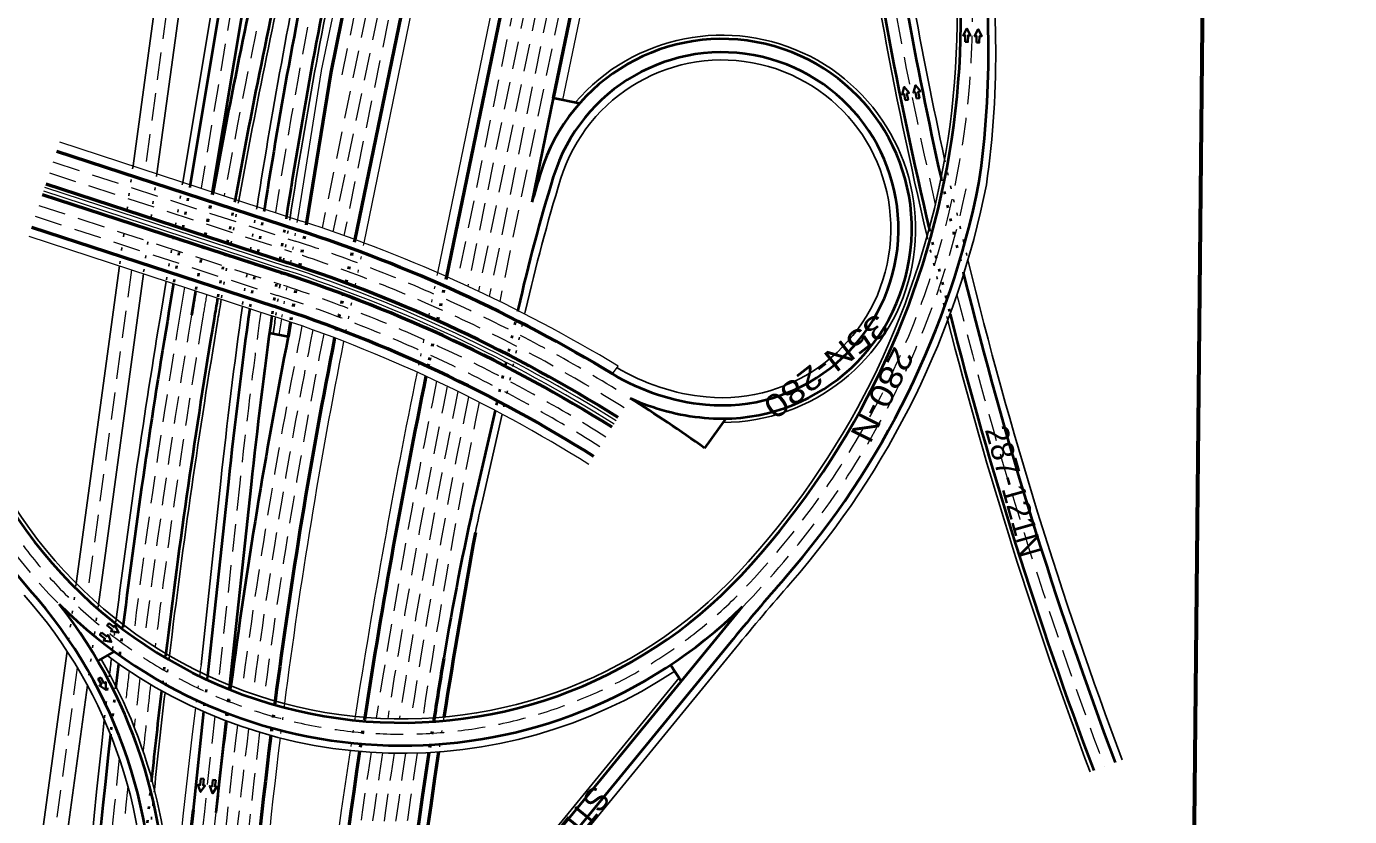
# Model space of a CAD drawing. Extents: x 2329387 to 2347382, y 6951580 to 6987999.
# Drawn here: x 2331366 to 2332753, y 6960345 to 6961173 of the extents above; entities that cross this region are included whole.
import ezdxf

# ---------------------------------------------------------------- set-up
doc = ezdxf.new("R2010")
doc.units = 0
doc.header["$LTSCALE"] = 9.6
doc.linetypes.add('DOTTED', pattern=[1.5, 0.3, -1.2])
doc.linetypes.add('MEDIUM_DASHED', pattern=[4.5, 3, -1.5])
for name, color, linetype, lineweight in [('26', 7, 'Continuous', 53), ('27', 7, 'Continuous', 40), ('41', 7, 'Continuous', 35), ('50', 7, 'MEDIUM_DASHED', 13), ('62', 7, 'Continuous', 60), ('63', 7, 'Continuous', 25)]:
    doc.layers.add(name, color=color, linetype=linetype, lineweight=lineweight)
doc.layers.add('40', color=7, linetype='Continuous')

msp = doc.modelspace()

# ---------------------------------------------------------------- linework, layer by layer
at = {"layer": '26', "lineweight": 13}
for p, q in [((2331724.458, 6961366.169), (2331675.26, 6961127.125)), ((2331802.815, 6961350.042), (2331719.775, 6960946.564)), ((2331883.115, 6961333.431), (2331797.054, 6960915.276)), ((2331973.227, 6961314.885), (2331928.251, 6961096.357)), ((2331675.253, 6961127.09), (2331650.138, 6960970.928)), ((2331400.74, 6961052.344), (2331654.558, 6960969.431)), ((2331383.972, 6961001.013), (2331637.791, 6960918.1)), ((2331385.214, 6961004.815), (2331639.033, 6960921.903)), ((2331368.447, 6960953.485), (2331622.265, 6960870.572)), ((2331633.423, 6960866.999), (2331630.744, 6960850.34)), ((2331980.676, 6960809.191), (2331986.398, 6960817.417))]:
    msp.add_line(p, q, dxfattribs=at)
at = {"layer": '26'}
for p, q in [((2331734.252, 6961364.153), (2331685.095, 6961125.305)), ((2331734.252, 6961364.153), (2331685.095, 6961125.305)), ((2331793.021, 6961352.058), (2331710.29, 6960950.086)), ((2331892.91, 6961331.415), (2331806.417, 6960911.164)), ((2331963.432, 6961316.901), (2331918.456, 6961098.373)), ((2331685.095, 6961125.305), (2331659.765, 6960967.813)), ((2331397.635, 6961042.838), (2331651.453, 6960959.925)), ((2331386.456, 6961008.618), (2331640.275, 6960925.705)), ((2331382.73, 6960997.211), (2331636.549, 6960914.298)), ((2331371.552, 6960962.99), (2331625.37, 6960880.078)), ((2331643.035, 6960863.784), (2331640.561, 6960848.405))]:
    msp.add_line(p, q, dxfattribs=at)
at = {"layer": '26', "linetype": 'DOTTED', "lineweight": 13}
for p, q in [((2331650.138, 6960970.928), (2331633.423, 6960866.999)), ((2331719.775, 6960946.564), (2331706.79, 6960883.472)), ((2331797.054, 6960915.276), (2331777.711, 6960821.292))]:
    msp.add_line(p, q, dxfattribs=at)
at = {"layer": '26', "linetype": 'DOTTED'}
for p, q in [((2331659.765, 6960967.813), (2331643.035, 6960863.784)), ((2331710.29, 6960950.086), (2331697.076, 6960885.882)), ((2331806.417, 6960911.164), (2331787.506, 6960819.276))]:
    msp.add_line(p, q, dxfattribs=at)
at = {"layer": '26'}
for centre, radius, start, end in [((2331155.652, 6959442.139), 1596.714, 58.88878, 71.90983), ((2331155.652, 6959442.139), 1560.714, 57.83887, 71.90983), ((2331155.652, 6959442.139), 1548.714, 57.83887, 71.90983), ((2331155.652, 6959442.139), 1512.714, 57.83887, 71.90983), ((2337309.03, 6959730.876), 5729.578, 168.76752, 172.62557), ((2339270.111, 6959279.267), 7639.437, 168.46618, 171.19128), ((2339270.111, 6959279.267), 7557.437, 169.60454, 171.09176), ((2339270.111, 6959279.267), 7567.437, 170.63176, 171.10996), ((2337309.03, 6959730.876), 5729.578, 172.98959, 183.29735), ((2339270.111, 6959279.267), 7639.437, 171.46189, 181.6147), ((2339270.111, 6959279.267), 7567.437, 171.38894, 177.10146), ((2339270.111, 6959279.267), 7557.437, 171.37243, 178.25098), ((2337309.03, 6959730.876), 5801.578, 173.85545, 181.55357)]:
    msp.add_arc(centre, radius, start, end, dxfattribs=at)
at = {"layer": '26', "lineweight": 13}
for centre, radius, start, end in [((2331155.652, 6959442.139), 1606.714, 58.86565, 71.90983), ((2331155.652, 6959442.139), 1552.714, 57.83887, 71.90983), ((2331155.652, 6959442.139), 1556.714, 57.83887, 71.90983), ((2331155.652, 6959442.139), 1502.714, 57.83887, 71.90983), ((2337309.03, 6959730.876), 5719.578, 168.78475, 172.63974), ((2339270.111, 6959279.267), 7649.437, 168.44885, 171.19593), ((2337309.03, 6959730.876), 5811.578, 172.35225, 172.42899), ((2337309.03, 6959730.876), 5811.578, 172.80217, 181.55357), ((2337309.03, 6959730.876), 5719.578, 173.00338, 183.29735), ((2339270.111, 6959279.267), 7649.437, 171.46588, 181.61718)]:
    msp.add_arc(centre, radius, start, end, dxfattribs=at)
at = {"layer": '26', "linetype": 'DOTTED'}
for centre, radius, start, end in [((2337309.03, 6959730.876), 5729.578, 168.37024, 168.76752), ((2339270.111, 6959279.267), 7639.437, 168.37024, 168.46618), ((2337309.03, 6959730.876), 5729.578, 172.62557, 172.98959), ((2339270.111, 6959279.267), 7639.437, 171.19128, 171.4619), ((2339270.111, 6959279.267), 7567.437, 171.10996, 171.38893)]:
    msp.add_arc(centre, radius, start, end, dxfattribs=at)
at = {"layer": '26', "linetype": 'DOTTED', "lineweight": 13}
for centre, radius, start, end in [((2337309.03, 6959730.876), 5719.578, 168.37024, 168.78475), ((2339270.111, 6959279.267), 7649.437, 168.37024, 168.44885), ((2337309.03, 6959730.876), 5811.578, 172.42899, 172.80218), ((2337309.03, 6959730.876), 5719.578, 172.63974, 173.00338), ((2339270.111, 6959279.267), 7649.437, 171.19593, 171.46588), ((2339270.111, 6959279.267), 7557.437, 171.09175, 171.37243)]:
    msp.add_arc(centre, radius, start, end, dxfattribs=at)
at = {"layer": '27', "lineweight": 25}
for p, q in [((2331775.493, 6962479.35), (2331530.014, 6961010.115)), ((2331512.68, 6960906.369), (2331507.632, 6960876.155)), ((2331864.699, 6960767.055), (2331844.423, 6960677.833)), ((2331569.876, 6960696.854), (2331549.146, 6960504.295)), ((2332109.524, 6960521.717), (2331847.333, 6960201.895)), ((2332050.366, 6960490.566), (2331827.226, 6960218.379))]:
    msp.add_line(p, q, dxfattribs=at)
at = {"layer": '27'}
for p, q in [((2331783.384, 6962478.032), (2331537.705, 6961007.603)), ((2331807.056, 6962474.077), (2331560.779, 6961000.065)), ((2331918.456, 6961098.373), (2331896.031, 6960989.412)), ((2331945.881, 6961092.729), (2331918.456, 6961098.373)), ((2331520.371, 6960903.857), (2331515.523, 6960874.836)), ((2331543.445, 6960896.319), (2331539.195, 6960870.881)), ((2331620.939, 6960852.273), (2331640.561, 6960848.405)), ((2331857.379, 6960770.946), (2331836.622, 6960679.607)), ((2332099.188, 6960762.344), (2332077.092, 6960731.428)), ((2331577.83, 6960695.998), (2331555.958, 6960492.83)), ((2331601.692, 6960693.429), (2331579.015, 6960482.786)), ((2332116.511, 6960564.941), (2331830.32, 6960215.843)), ((2331458.2, 6960518.373), (2331440.929, 6960508.288)), ((2332103.417, 6960526.886), (2331841.147, 6960206.967)), ((2332041.332, 6960504.221), (2332052.676, 6960487.075)), ((2331551.902, 6960455.152), (2331540.782, 6960351.86)), ((2331575.02, 6960445.673), (2331564.644, 6960349.291))]:
    msp.add_line(p, q, dxfattribs=at)
at = {"layer": '27', "linetype": 'DOTTED', "lineweight": 25}
for p, q in [((2331530.014, 6961010.115), (2331512.68, 6960906.369)), ((2331889.412, 6960875.801), (2331864.699, 6960767.055))]:
    msp.add_line(p, q, dxfattribs=at)
at = {"layer": '27', "linetype": 'DOTTED'}
for p, q in [((2331537.705, 6961007.603), (2331520.371, 6960903.857)), ((2331560.779, 6961000.065), (2331543.445, 6960896.319)), ((2331881.613, 6960877.581), (2331857.379, 6960770.946)), ((2331555.958, 6960492.83), (2331551.902, 6960455.152)), ((2331579.015, 6960482.786), (2331575.02, 6960445.673))]:
    msp.add_line(p, q, dxfattribs=at)
at = {"layer": '27'}
for centre, radius, start, end in [((2339406.145, 6959556.474), 7976, 170.51466, 170.51466), ((2331488.314, 6961182.977), 857.473, 316.98269, 21.88176), ((2336798.354, 6962013.709), 4607.662, 187.82614, 193.20332), ((2336798.354, 6962013.709), 4583.662, 187.97272, 192.59319), ((2331429.011, 6961146.766), 945.765, 351.62744, 9.92921), ((2339406.145, 6959556.474), 7976, 167.39024, 169.57492), ((2339406.145, 6959556.474), 7952, 167.39024, 169.5982), ((2337567.201, 6960051.195), 6023.98, 168.01367, 171.10971), ((2337567.201, 6960051.195), 5999.98, 168.01367, 171.14683), ((2332095.311, 6960961.306), 199, 264.63628, 162.90746), ((2332095.311, 6960961.306), 185, 264.63628, 162.90746), ((2333743.985, 6960454.343), 1909.859, 162.90746, 167.19654), ((2333743.985, 6960454.343), 1923.859, 162.90746, 163.85178), ((2331488.314, 6961182.977), 893.473, 318.86471, 348.77516), ((2336798.354, 6962013.709), 4583.662, 193.88538, 200.589), ((2339406.145, 6959556.474), 7976, 170.32943, 170.51466), ((2339406.145, 6959556.474), 7952, 170.35503, 170.51466), ((2339406.145, 6959556.474), 8000, 170.51466, 172.89271), ((2337567.201, 6960051.195), 6023.98, 172.11324, 173.85533), ((2339406.145, 6959556.474), 7952, 170.51466, 173.06921), ((2337567.201, 6960051.195), 5999.98, 172.15449, 173.85532), ((2336798.354, 6962013.709), 4607.662, 194.34791, 200.589), ((2337309.03, 6959730.876), 5777.578, 168.84726, 172.52817), ((2332099.517, 6961006.109), 230, 238.88879, 264.63628), ((2331155.652, 6959442.139), 1584.714, 54.44704, 57.83887), ((2332099.517, 6961006.109), 244, 245.72346, 264.63628), ((2331759.916, 6960929.551), 486, 207.17559, 316.98269), ((2331760.015, 6960929.359), 522, 207.17524, 221.62086), ((2334630.184, 6960044.76), 2864.789, 167.19678, 170.63176), ((2330989.258, 6960244.547), 509.035, 355.35626, 41.62086), ((2334318.881, 6958710.645), 2864.789, 138.86471, 140.65505), ((2331759.916, 6960929.551), 510, 225.19474, 314.36331), ((2330989.258, 6960244.547), 523.035, 355.35626, 38.15909), ((2339406.145, 6959556.474), 8000, 173.18807, 173.3576), ((2339406.145, 6959556.474), 7952, 173.35147, 174.02309), ((2337309.03, 6959730.876), 5777.578, 172.89618, 173.85545), ((2339406.145, 6959556.474), 8000, 173.72103, 179.41614)]:
    msp.add_arc(centre, radius, start, end, dxfattribs=at)
at = {"layer": '27', "lineweight": 25}
for centre, radius, start, end in [((2331488.314, 6961182.977), 853.473, 316.98269, 21.88176), ((2337081.285, 6962065.532), 4898.95, 187.63559, 193.12349), ((2336798.354, 6962013.709), 4575.662, 188.03429, 192.35956), ((2337567.201, 6960051.195), 6031.98, 168.01367, 171.0974), ((2331388.291, 6961146.248), 993.984, 351.97584, 9.5406), ((2339406.145, 6959556.474), 7948, 167.39024, 169.60209), ((2337567.201, 6960051.195), 5995.98, 168.01367, 171.15332), ((2332095.311, 6960961.306), 203, 270.28029, 139.31038), ((2332095.311, 6960961.306), 177, 264.63628, 162.90746), ((2333743.985, 6960454.343), 1901.859, 162.90746, 167.19678), ((2331488.314, 6961182.977), 901.473, 318.86661, 348.77516), ((2336798.354, 6962013.709), 4575.662, 193.71669, 200.589), ((2339406.145, 6959556.474), 8008, 170.51466, 172.85862), ((2339406.145, 6959556.474), 7948, 170.35931, 170.51466), ((2337567.201, 6960051.195), 6031.98, 172.09956, 173.85532), ((2339406.145, 6959556.474), 7948, 170.51466, 173.08188), ((2337567.201, 6960051.195), 5995.98, 172.16092, 172.32966), ((2336798.354, 6962013.709), 4611.662, 194.41946, 200.589), ((2332099.517, 6961006.109), 222, 238.88879, 264.63628), ((2331759.916, 6960929.551), 482, 207.17559, 316.98269), ((2334630.184, 6960044.76), 2856.789, 167.19678, 167.91345), ((2334324.989, 6958705.476), 2864.789, 138.86661, 140.65505), ((2330989.258, 6960244.547), 501.035, 355.35626, 41.62086), ((2331759.916, 6960929.551), 518, 233.34606, 303.49023), ((2330989.258, 6960244.547), 527.035, 355.35626, 30.28163), ((2339406.145, 6959556.474), 8008, 173.15672, 173.2734), ((2339406.145, 6959556.474), 7948, 173.36327, 174.09944), ((2339406.145, 6959556.474), 8008, 173.61844, 179.41614)]:
    msp.add_arc(centre, radius, start, end, dxfattribs=at)
at = {"layer": '27', "linetype": 'DOTTED', "lineweight": 25}
for centre, radius, start, end in [((2336798.354, 6962013.709), 4575.662, 192.35956, 193.71669), ((2339406.145, 6959556.474), 7948, 169.60209, 170.35931), ((2337567.201, 6960051.195), 6031.98, 171.0974, 172.09956), ((2337567.201, 6960051.195), 5995.98, 171.15332, 172.16092), ((2336798.354, 6962013.709), 4611.662, 193.29457, 194.41946), ((2339406.145, 6959556.474), 8008, 172.85862, 173.15672), ((2339406.145, 6959556.474), 7948, 173.08188, 173.36328), ((2339406.145, 6959556.474), 8008, 173.2739, 173.61844), ((2339406.145, 6959556.474), 7948, 174.09944, 174.88074)]:
    msp.add_arc(centre, radius, start, end, dxfattribs=at)
at = {"layer": '27', "linetype": 'DOTTED'}
for centre, radius, start, end in [((2336798.354, 6962013.709), 4583.662, 192.59319, 193.88539), ((2339406.145, 6959556.474), 7976, 169.57492, 170.32943), ((2339406.145, 6959556.474), 7952, 169.5982, 170.35503), ((2337567.201, 6960051.195), 6023.98, 171.10971, 172.11324), ((2337567.201, 6960051.195), 5999.98, 171.14683, 172.15449), ((2336798.354, 6962013.709), 4607.662, 193.20332, 194.34791), ((2339406.145, 6959556.474), 8000, 172.89271, 173.18807), ((2339406.145, 6959556.474), 7952, 173.06921, 173.35147), ((2339406.145, 6959556.474), 8000, 173.3576, 173.72103), ((2337309.03, 6959730.876), 5777.578, 172.52818, 172.89618), ((2339406.145, 6959556.474), 7952, 174.02309, 174.70032)]:
    msp.add_arc(centre, radius, start, end, dxfattribs=at)
at = {"layer": '27', "linetype": 'DOTTED', "lineweight": 13}
msp.add_arc((2339406.145, 6959556.474), 8008, 173.2734, 173.2739, dxfattribs=at)
at = {"layer": '41'}
for points in [[(2332350.116, 6961157.267), (2332353.116, 6961157.207), (2332353.251, 6961164.013), (2332355.688, 6961163.965), (2332352.052, 6961171.238), (2332348.131, 6961164.114), (2332350.251, 6961164.072)], [(2332362.087, 6961156.508), (2332365.087, 6961156.448), (2332365.222, 6961163.254), (2332367.659, 6961163.206), (2332364.023, 6961170.479), (2332360.103, 6961163.355), (2332362.222, 6961163.313)], [(2332287.463, 6961096.002), (2332290.408, 6961096.579), (2332289.097, 6961103.259), (2332291.489, 6961103.728), (2332286.395, 6961110.066), (2332284.073, 6961102.273), (2332286.153, 6961102.681)], [(2332299.323, 6961097.796), (2332302.268, 6961098.373), (2332300.958, 6961105.053), (2332303.349, 6961105.522), (2332298.255, 6961111.86), (2332295.933, 6961104.067), (2332298.013, 6961104.475)], [(2331452.512, 6960547.832), (2331450.687, 6960545.45), (2331456.091, 6960541.31), (2331454.608, 6960539.375), (2331462.622, 6960537.997), (2331459.204, 6960545.375), (2331457.915, 6960543.692)], [(2331444.968, 6960538.105), (2331443.144, 6960535.723), (2331448.547, 6960531.584), (2331447.065, 6960529.649), (2331455.079, 6960528.27), (2331451.661, 6960535.648), (2331450.372, 6960533.966)], [(2331444.113, 6960491.073), (2331441.477, 6960489.639), (2331444.728, 6960483.659), (2331442.587, 6960482.495), (2331449.346, 6960477.974), (2331449.227, 6960486.105), (2331447.364, 6960485.092)], [(2331552.052, 6960384.709), (2331549.073, 6960385.07), (2331548.254, 6960378.313), (2331545.834, 6960378.606), (2331548.72, 6960371.003), (2331553.337, 6960377.697), (2331551.233, 6960377.952)], [(2331564.539, 6960383.239), (2331561.56, 6960383.6), (2331560.741, 6960376.843), (2331558.322, 6960377.136), (2331561.207, 6960369.534), (2331565.824, 6960376.227), (2331563.72, 6960376.482)]]:
    msp.add_lwpolyline(points, close=True, dxfattribs=at)
at = {"layer": '50'}
for p, q in [((2331795.22, 6962476.054), (2331549.242, 6961003.834)), ((2331757.76, 6961359.315), (2331676.038, 6960962.247)), ((2331746.006, 6961361.734), (2331696.848, 6961122.886)), ((2331769.513, 6961356.896), (2331687.474, 6960958.284)), ((2331780.211, 6961349.347), (2331698.891, 6960954.23)), ((2331904.664, 6961328.996), (2331817.635, 6960906.143)), ((2331916.417, 6961326.577), (2331828.834, 6960901.027)), ((2331928.171, 6961324.158), (2331840.013, 6960895.817)), ((2331939.925, 6961321.739), (2331851.173, 6960890.511)), ((2331951.678, 6961319.32), (2331862.312, 6960885.108)), ((2331393.909, 6961031.431), (2331647.727, 6960948.519)), ((2331390.182, 6961020.024), (2331644.001, 6960937.112)), ((2331379.004, 6960985.804), (2331632.822, 6960902.891)), ((2331375.278, 6960974.397), (2331629.096, 6960891.485)), ((2331531.908, 6960900.088), (2331527.359, 6960872.859)), ((2331589.761, 6960694.714), (2331567.468, 6960487.637)), ((2331563.444, 6960450.257), (2331552.713, 6960350.575))]:
    msp.add_line(p, q, dxfattribs=at)
for centre, radius, start, end in [((2336798.354, 6962013.709), 4595.662, 182.32731, 192.91301), ((2331488.314, 6961182.977), 869.473, 316.98269, 21.88176), ((2339406.145, 6959556.474), 7964, 167.39024, 169.58654), ((2337567.201, 6960051.195), 6011.98, 168.01367, 171.12823), ((2331488.314, 6961182.977), 881.473, 315.46714, 348.77516), ((2331155.652, 6959442.139), 1584.714, 58.46734, 71.90983), ((2331155.652, 6959442.139), 1572.714, 57.83887, 71.90983), ((2331155.652, 6959442.139), 1536.714, 57.83887, 71.90983), ((2339406.145, 6959556.474), 7964, 170.34221, 170.51466), ((2331155.652, 6959442.139), 1524.714, 57.83887, 71.90983), ((2336798.354, 6962013.709), 4595.662, 194.12418, 200.589), ((2337567.201, 6960051.195), 6011.98, 172.13383, 173.85544), ((2339406.145, 6959556.474), 7988, 170.51466, 172.94123), ((2339406.145, 6959556.474), 7976, 170.51466, 172.98675), ((2339406.145, 6959556.474), 7964, 170.51466, 173.02937), ((2337309.03, 6959730.876), 5765.578, 168.71169, 172.55713), ((2337309.03, 6959730.876), 5753.578, 168.72924, 172.58299), ((2337309.03, 6959730.876), 5741.578, 168.74784, 172.6058), ((2339270.111, 6959279.267), 7627.437, 168.48775, 171.1836), ((2339270.111, 6959279.267), 7615.437, 168.51018, 171.17362), ((2339270.111, 6959279.267), 7603.437, 168.53347, 171.1613), ((2339270.111, 6959279.267), 7591.437, 168.55764, 171.14662), ((2339270.111, 6959279.267), 7579.437, 168.5827, 171.12952), ((2331759.916, 6960929.551), 510, 207.17525, 225.19472), ((2331759.916, 6960929.551), 498, 207.17525, 316.98269), ((2339406.145, 6959556.474), 7988, 173.23282, 173.49467), ((2339406.145, 6959556.474), 7976, 173.27491, 173.64751), ((2339406.145, 6959556.474), 7964, 173.31444, 173.82091), ((2337309.03, 6959730.876), 5765.578, 172.92379, 183.29735), ((2337309.03, 6959730.876), 5753.578, 172.94854, 183.29735), ((2337309.03, 6959730.876), 5741.578, 172.97047, 183.29735), ((2339406.145, 6959556.474), 7988, 173.8931, 179.41614), ((2339270.111, 6959279.267), 7627.437, 171.45517, 181.61172), ((2339270.111, 6959279.267), 7615.437, 171.44631, 181.60872), ((2339270.111, 6959279.267), 7603.437, 171.43529, 181.60572), ((2339270.111, 6959279.267), 7591.437, 171.42207, 177.10146), ((2339270.111, 6959279.267), 7579.437, 171.40663, 177.10146), ((2339406.145, 6959556.474), 7976, 174.09518, 179.41614), ((2337309.03, 6959730.876), 5789.578, 173.85545, 183.29735), ((2337309.03, 6959730.876), 5777.578, 173.85545, 183.29735)]:
    msp.add_arc(centre, radius, start, end, dxfattribs=at)
at = {"layer": '62'}
msp.add_lwpolyline([(2332642.295, 6965522.154), (2332560.849, 6957416.973), (2330660.943, 6957436.065), (2330739.467, 6965250.394)], close=True, dxfattribs=at)
at = {"layer": '63'}
for p, q in [((2331583.039, 6961607.79), (2331502.947, 6961018.957)), ((2331548.281, 6961545.165), (2331477.824, 6961027.163)), ((2331463.576, 6960922.409), (2331418.298, 6960589.521)), ((2331488.699, 6960914.203), (2331441.562, 6960567.647)), ((2331430.021, 6960482.799), (2331314.438, 6959633.029))]:
    msp.add_line(p, q, dxfattribs=at)
at = {"layer": '63', "linetype": 'MEDIUM_DASHED', "lineweight": 13}
for p, q in [((2331565.355, 6961574.235), (2331490.386, 6961023.06)), ((2331476.138, 6960918.306), (2331429.886, 6960578.262)), ((2331419.434, 6960501.422), (2331301.557, 6959634.781))]:
    msp.add_line(p, q, dxfattribs=at)
at = {"layer": '63', "linetype": 'DOTTED'}
for p, q in [((2331477.824, 6961027.163), (2331463.576, 6960922.409)), ((2331502.947, 6961018.957), (2331488.699, 6960914.203)), ((2331418.298, 6960589.521), (2331408.66, 6960518.661)), ((2331441.562, 6960567.647), (2331430.021, 6960482.799))]:
    msp.add_line(p, q, dxfattribs=at)
at = {"layer": '63'}
msp.add_lwpolyline([(2331408.66, 6960518.661), (2331342.19, 6960029.976), (2331332.504, 6959958.761)], dxfattribs=at)

# ---------------------------------------------------------------- texts
at = {"layer": '40'}
for s, rotation, width, p in [('35N-280', 217.914, 1.25, (2332257.814, 6960873.882)), ('280-N', 243.24, 1.2, (2332276.317, 6960839.441))]:
    msp.add_text(s, height=24, rotation=rotation, dxfattribs=dict(at, width=width)).set_placement(p)
for s, rotation, p in [('287-121N', 285.862, (2332370.683, 6960750.887)), ('STEADMAN', 230.757, (2331961.07, 6960379.281))]:
    msp.add_text(s, height=24, rotation=rotation, dxfattribs=at).set_placement(p)

doc.saveas('drawing.dxf')
